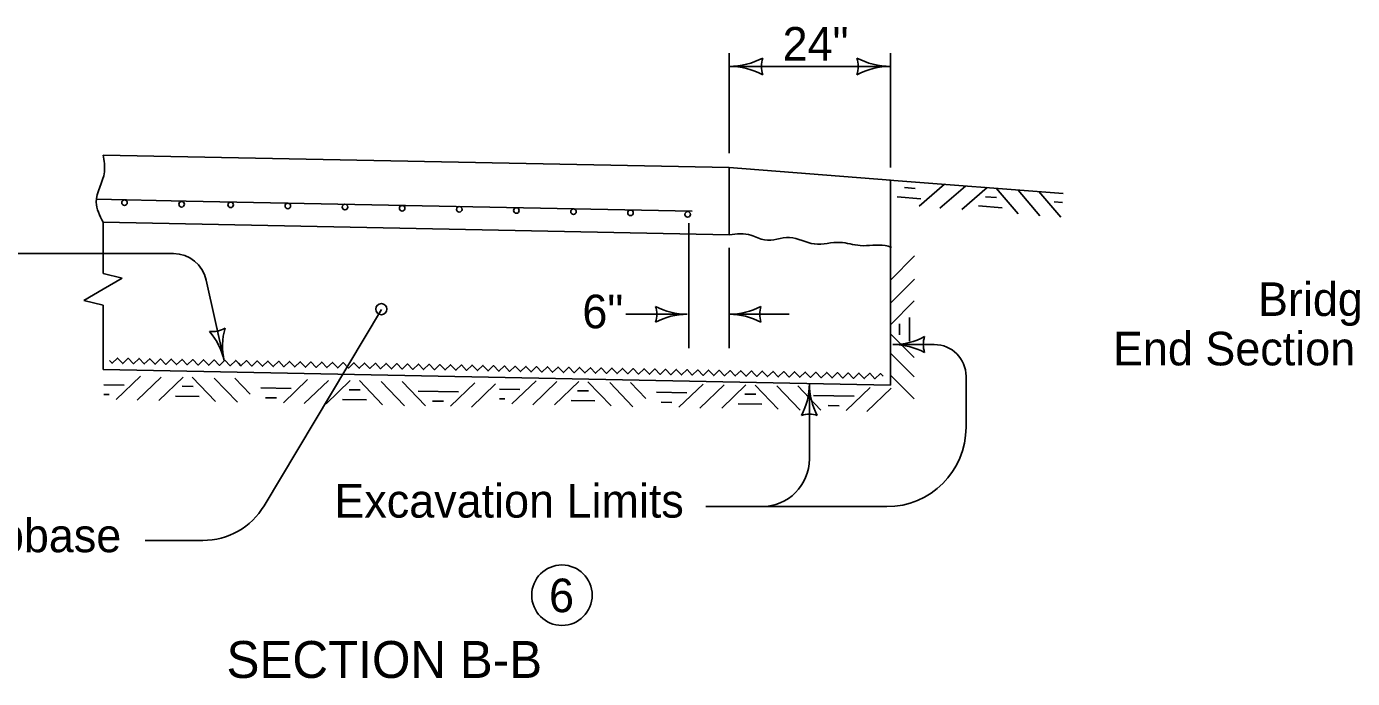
# Model space of a CAD drawing. Extents: x 10130 to 81668, y 5440 to 21644.
# Drawn here: x 17701 to 18491, y 6575 to 6964 of the extents above; entities that cross this region are included whole.
import ezdxf

# ---------------------------------------------------------------- set-up
doc = ezdxf.new("R2010")
doc.units = 0
doc.layers.add('dsnStdBlockModified', color=7, linetype='Continuous')
doc.layers.add('dsnStdBorder', color=7, linetype='Continuous')

msp = doc.modelspace()

# ---------------------------------------------------------------- linework, layer by layer
at = {"layer": 'dsnStdBorder'}
for p, q in [((18119.72, 6888.17), (18119.72, 6947.87)), ((18215.72, 6879.61), (18215.72, 6947.87)), ((18119.72, 6939.89), (18215.72, 6939.89)), ((18119.72, 6879.61), (17746.79, 6887.09)), ((17746.79, 6887.09), (18119.72, 6879.61)), ((18119.72, 6839.6), (18119.72, 6879.61)), ((18119.72, 6879.61), (18119.72, 6839.6)), ((18119.72, 6879.61), (18215.72, 6872.22)), ((18215.08, 6872.21), (18318.54, 6864.25)), ((18215.72, 6749.95), (18215.72, 6872.17)), ((18247.99, 6869.68), (18232.8, 6856.67)), ((18260.38, 6868.5), (18245.2, 6855.49)), ((18273.37, 6867.73), (18258.18, 6854.71)), ((18278.76, 6867.31), (18291.78, 6852.13)), ((18291.72, 6866.09), (18304.73, 6850.9)), ((18304.15, 6865.36), (18317.16, 6850.17)), ((17796.26, 6859.66), (17742.82, 6860.73)), ((18097.62, 6853.61), (17796.26, 6859.66)), ((17746.79, 6847.08), (18119.72, 6839.6)), ((17746.79, 6847.08), (18119.72, 6839.6)), ((17746.79, 6846.82), (17746.79, 6816.56)), ((18095.72, 6772.06), (18095.72, 6846.53)), ((18119.72, 6772.06), (18119.72, 6831.76)), ((17679.98, 6828.35), (17788.77, 6828.35)), ((18215.94, 6812.84), (18230.08, 6826.98)), ((17746.79, 6816.56), (17758.13, 6813.73)), ((17746.79, 6807.11), (17735.44, 6800.49)), ((17758.13, 6813.73), (17746.79, 6807.11)), ((17808.3, 6812.66), (17818.91, 6764.53)), ((18215.94, 6799.04), (18230.08, 6813.18)), ((17735.44, 6800.49), (17746.79, 6797.66)), ((18215.72, 6786.03), (18229.86, 6800.17)), ((17746.79, 6797.66), (17746.79, 6759.34)), ((17842.76, 6678.21), (17912.58, 6794.99)), ((18094.73, 6792.24), (18058.19, 6792.24)), ((18155.5, 6792.24), (18119.72, 6792.24)), ((17814.52, 6784.45), (17815.64, 6779.34)), ((18215.72, 6780.62), (18229.86, 6766.48)), ((18215.72, 6769.04), (18229.86, 6754.9)), ((18241.85, 6774.21), (18217.13, 6774.21)), ((17746.79, 6759.34), (18215.7, 6749.93)), ((17769.06, 6755.32), (17754.64, 6741.47)), ((17781.5, 6754.85), (17767.08, 6740.99)), ((17794.51, 6754.81), (17780.09, 6740.96)), ((17799.92, 6754.71), (17813.78, 6740.28)), ((17812.92, 6754.22), (17826.78, 6739.8)), ((17825.38, 6754.19), (17834.48, 6744.72)), ((17868.59, 6753.33), (17854.17, 6739.47)), ((17881.03, 6752.85), (17866.61, 6739)), ((17894.04, 6752.82), (17879.62, 6738.96)), ((17899.45, 6752.71), (17913.31, 6738.28)), ((17912.46, 6752.22), (17926.31, 6737.8)), ((17924.91, 6752.2), (17938.76, 6737.77)), ((18004.66, 6752.69), (17990.24, 6738.83)), ((18017.1, 6752.21), (18002.68, 6738.36)), ((18030.11, 6752.18), (18015.69, 6738.32)), ((18035.52, 6752.07), (18049.38, 6737.65)), ((18048.52, 6751.58), (18062.38, 6737.16)), ((18060.98, 6751.56), (18070.08, 6742.08)), ((18215.72, 6755.98), (18229.86, 6741.84)), ((18260.76, 6755.3), (18260.76, 6724.95)), ((17968.12, 6751.33), (17953.7, 6737.47)), ((17980.57, 6750.85), (17966.14, 6737)), ((18104.19, 6750.69), (18089.77, 6736.83)), ((18116.64, 6750.21), (18102.21, 6736.36)), ((18129.64, 6750.18), (18115.22, 6736.32)), ((18135.06, 6750.07), (18148.91, 6735.65)), ((18148.06, 6749.58), (18161.91, 6735.16)), ((18160.51, 6749.56), (18174.36, 6735.14)), ((18167.45, 6750.9), (18167.45, 6706.04)), ((18203.72, 6748.69), (18189.3, 6734.84)), ((18216.17, 6748.22), (18201.74, 6734.36)), ((18213.49, 6677.68), (18105.72, 6677.68)), ((17771.97, 6657.5), (17806.25, 6657.5))]:
    msp.add_line(p, q, dxfattribs=at)
for points in [[(18219.73, 6862.12), (18233.88, 6861.04)], [(18224, 6867.67), (18230.51, 6867.17)], [(18272.39, 6862.29), (18278.9, 6861.79)], [(18268.12, 6856.74), (18282.27, 6855.66)], [(18313.28, 6859.17), (18318.12, 6858.79)], [(18221.21, 6780.06), (18221.21, 6786.59)], [(18227.07, 6776.23), (18227.07, 6790.42)], [(17750.6, 6764.67), (17752.17, 6763.04), (17755.43, 6766.17), (17758.57, 6762.91), (17761.83, 6766.05), (17764.96, 6762.78), (17768.23, 6765.92), (17771.36, 6762.65), (17774.63, 6765.79), (17777.76, 6762.52), (17781.03, 6765.66), (17784.16, 6762.4), (17787.42, 6765.53), (17790.56, 6762.27), (17793.82, 6765.4), (17796.96, 6762.14), (17800.22, 6765.27), (17803.36, 6762.01), (17806.62, 6765.15), (17809.76, 6761.88), (17813.02, 6765.02), (17816.15, 6761.75), (17819.42, 6764.89), (17822.55, 6761.63), (17825.82, 6764.76), (17827.38, 6763.13)], [(17827.38, 6763.13), (17828.95, 6761.5), (17832.22, 6764.63), (17835.35, 6761.37), (17838.61, 6764.5), (17841.75, 6761.24), (17845.01, 6764.38), (17848.15, 6761.11), (17851.41, 6764.25), (17854.55, 6760.98), (17857.81, 6764.12), (17860.95, 6760.86), (17864.21, 6763.99), (17867.34, 6760.73), (17870.61, 6763.86), (17873.74, 6760.6), (17877.01, 6763.73), (17880.14, 6760.47), (17883.4, 6763.6), (17886.54, 6760.34), (17889.8, 6763.48), (17892.94, 6760.21), (17896.2, 6763.35), (17899.34, 6760.08), (17902.6, 6763.22), (17904.17, 6761.59)], [(17904.17, 6761.59), (17905.74, 6759.96), (17909, 6763.09), (17912.13, 6759.83), (17915.4, 6762.96), (17918.53, 6759.7), (17921.8, 6762.83), (17924.93, 6759.57), (17928.2, 6762.71), (17931.33, 6759.44), (17934.59, 6762.58), (17937.73, 6759.31), (17940.99, 6762.45), (17944.13, 6759.19), (17947.39, 6762.32), (17950.53, 6759.06), (17953.79, 6762.19), (17956.93, 6758.93), (17960.19, 6762.06), (17963.32, 6758.8), (17966.59, 6761.94), (17969.72, 6758.67), (17972.99, 6761.81), (17976.12, 6758.54), (17979.39, 6761.68), (17980.95, 6760.05)], [(17980.99, 6759.95), (17982.56, 6758.31), (17985.82, 6761.45), (17988.95, 6758.19), (17992.22, 6761.32), (17995.35, 6758.06), (17998.62, 6761.19), (18001.75, 6757.93), (18005.01, 6761.06), (18008.15, 6757.8), (18011.41, 6760.94), (18014.55, 6757.67), (18017.81, 6760.81), (18020.95, 6757.54), (18024.21, 6760.68), (18027.35, 6757.41), (18030.61, 6760.55), (18033.74, 6757.29), (18037.01, 6760.42), (18040.14, 6757.16), (18043.41, 6760.29), (18046.54, 6757.03), (18049.81, 6760.16), (18052.94, 6756.9), (18056.2, 6760.04), (18057.77, 6758.4)], [(18057.77, 6758.4), (18059.34, 6756.77), (18062.6, 6759.91), (18065.74, 6756.64), (18069, 6759.78), (18072.14, 6756.52), (18075.4, 6759.65), (18078.54, 6756.39), (18081.8, 6759.52), (18084.93, 6756.26), (18088.2, 6759.39), (18091.33, 6756.13), (18094.6, 6759.27), (18097.73, 6756), (18101, 6759.14), (18104.13, 6755.87), (18107.39, 6759.01), (18110.53, 6755.74), (18113.79, 6758.88), (18116.93, 6755.62), (18120.19, 6758.75), (18123.33, 6755.49), (18126.59, 6758.62), (18129.73, 6755.36), (18132.99, 6758.49), (18134.56, 6756.86)], [(18134.56, 6756.86), (18136.12, 6755.23), (18139.39, 6758.37), (18142.52, 6755.1), (18145.79, 6758.24), (18148.92, 6754.97), (18152.19, 6758.11), (18155.32, 6754.85), (18158.58, 6757.98), (18161.72, 6754.72), (18164.98, 6757.85), (18168.12, 6754.59), (18171.38, 6757.72), (18174.52, 6754.46), (18177.78, 6757.6), (18180.92, 6754.33), (18184.18, 6757.47), (18187.31, 6754.2), (18190.58, 6757.34), (18193.71, 6754.08), (18196.98, 6757.21), (18200.11, 6753.95), (18203.37, 6757.08), (18206.51, 6753.82), (18209.77, 6756.95), (18211.34, 6755.32)], [(17747.22, 6744.49), (17750.49, 6744.42)], [(17747.34, 6750.28), (17759.37, 6750.04)], [(17793.84, 6749.33), (17800.37, 6749.2)], [(17840.84, 6748.41), (17858.9, 6748.05)], [(17893.37, 6747.33), (17899.91, 6747.2)], [(17934.38, 6746.53), (17958.43, 6746.05)], [(17982.94, 6747.65), (17994.97, 6747.41)], [(18029.44, 6746.69), (18035.97, 6746.56)], [(18076.44, 6745.77), (18094.5, 6745.41)], [(18128.98, 6744.69), (18135.51, 6744.56)], [(18169.98, 6743.89), (18194.03, 6743.41)], [(17789.89, 6743.55), (17804.08, 6743.27)], [(17843.49, 6742.55), (17850.02, 6742.42)], [(17889.43, 6741.55), (17903.62, 6741.27)], [(17943.02, 6740.56), (17949.55, 6740.43)], [(17982.82, 6741.85), (17986.09, 6741.78)], [(18025.5, 6740.91), (18039.68, 6740.63)], [(18079.09, 6739.92), (18085.62, 6739.79)], [(18125.03, 6738.92), (18139.22, 6738.63)], [(18178.62, 6737.92), (18185.16, 6737.79)]]:
    msp.add_lwpolyline(points, dxfattribs=at)
for centre, radius in [((17759.55, 6858.72), 1.65), ((17793.59, 6857.79), 1.65), ((17822.81, 6857.46), 1.65), ((17856.84, 6856.78), 1.65), ((17890.87, 6856.1), 1.65), ((17924.91, 6855.41), 1.65), ((17958.94, 6854.73), 1.65), ((17992.97, 6854.05), 1.65), ((18027, 6853.37), 1.65), ((18060.91, 6852.67), 1.65), ((18094.95, 6851.75), 1.65), ((17912.56, 6795.31), 3.31), ((18020.08, 6624.9), 18)]:
    msp.add_circle(centre, radius, dxfattribs=at)
for centre, radius, start, end in [((18119.72, 6982.39), 42.5, 270, 298.07249), ((18155.35, 6939.89), 16.42, 162.26665, 197.73335), ((18180.08, 6939.89), 16.42, 342.26665, 17.73335), ((18215.72, 6982.39), 42.5, 241.92751, 270), ((18180.08, 6939.89), 16.42, 342.26665, 17.73335), ((18215.72, 6982.39), 42.5, 241.92751, 270), ((18119.72, 6897.39), 42.5, 61.92751, 90), ((18215.72, 6897.39), 42.5, 90, 118.07249), ((18215.72, 6897.39), 42.5, 90, 118.07249), ((17788.77, 6808.35), 20, 12.43134, 90), ((18061.04, 6792.24), 15.52, 342.26665, 17.73335), ((18094.73, 6832.41), 40.18, 241.92751, 270), ((18061.04, 6792.24), 15.52, 342.26665, 17.73335), ((18094.73, 6832.41), 40.18, 241.92751, 270), ((18094.73, 6752.06), 40.18, 90, 118.07249), ((18094.73, 6752.06), 40.18, 90, 118.07249), ((18119.72, 6832.41), 40.18, 270, 298.07249), ((18119.72, 6752.06), 40.18, 61.92751, 90), ((18153.4, 6792.24), 15.52, 162.26665, 197.73335), ((17811.67, 6797.43), 15.52, 264.68499, 300.15169), ((17858.15, 6773.17), 40.18, 164.34585, 192.41834), ((17779.68, 6755.89), 40.18, 12.41834, 40.49083), ((18217.13, 6814.39), 40.18, 270, 298.07249), ((18217.13, 6814.39), 40.18, 270, 298.07249), ((18250.82, 6774.21), 15.52, 162.26665, 197.73335), ((18250.82, 6774.21), 15.52, 162.26665, 197.73335), ((18217.13, 6734.04), 40.18, 61.92751, 90), ((18217.13, 6734.04), 40.18, 61.92751, 90), ((18241.85, 6755.31), 18.91, 0, 90), ((18127.27, 6750.9), 40.18, 331.92751, 360), ((18207.62, 6750.9), 40.18, 180, 208.07249), ((18167.45, 6717.21), 15.52, 72.26665, 107.73335), ((18213.49, 6724.94), 47.27, 270, 360), ((18139.09, 6706.04), 28.36, 270, 360), ((17806.25, 6700.04), 42.54, 270, 329.12488)]:
    msp.add_arc(centre, radius, start, end, dxfattribs=at)
for points in [[(17746.79, 6887.09), (17747.61, 6877.07), (17742.73, 6859.03), (17746.79, 6847.08)], [(17746.79, 6887.09), (17747.61, 6877.07), (17742.73, 6859.03), (17746.79, 6847.08)], [(18119.72, 6839.6), (18132.66, 6839.39), (18140.79, 6836.52), (18155.62, 6837.95), (18170.45, 6834.13), (18185.75, 6835.08), (18197.71, 6833.17), (18212.53, 6833.17), (18216.36, 6832.21)]]:
    msp.add_spline(points, degree=3, dxfattribs=at)

# ---------------------------------------------------------------- texts
at = {"layer": 'dsnStdBlockModified'}
for s, height, p in [('24"', 20, (18151.5, 6943.35)), ('6"', 20, (18032.25, 6783.92)), ('Excavation Limits', 20, (17884.56, 6671.12)), ('Modified Subbase', 20, (17543.54, 6650.52)), ('6', 20, (18012.39, 6614.78)), ('SECTION B-B', 22, (17820.32, 6575.61))]:
    msp.add_text(s, height=height, dxfattribs=at).set_placement(p)
at = {"layer": 'dsnStdBorder'}
for s, p in [('Bridge Rail', (18434.61, 6791.25)), ('End Section (typ.)', (18348.24, 6761.8))]:
    msp.add_text(s, height=20, dxfattribs=at).set_placement(p)

doc.saveas('drawing.dxf')
